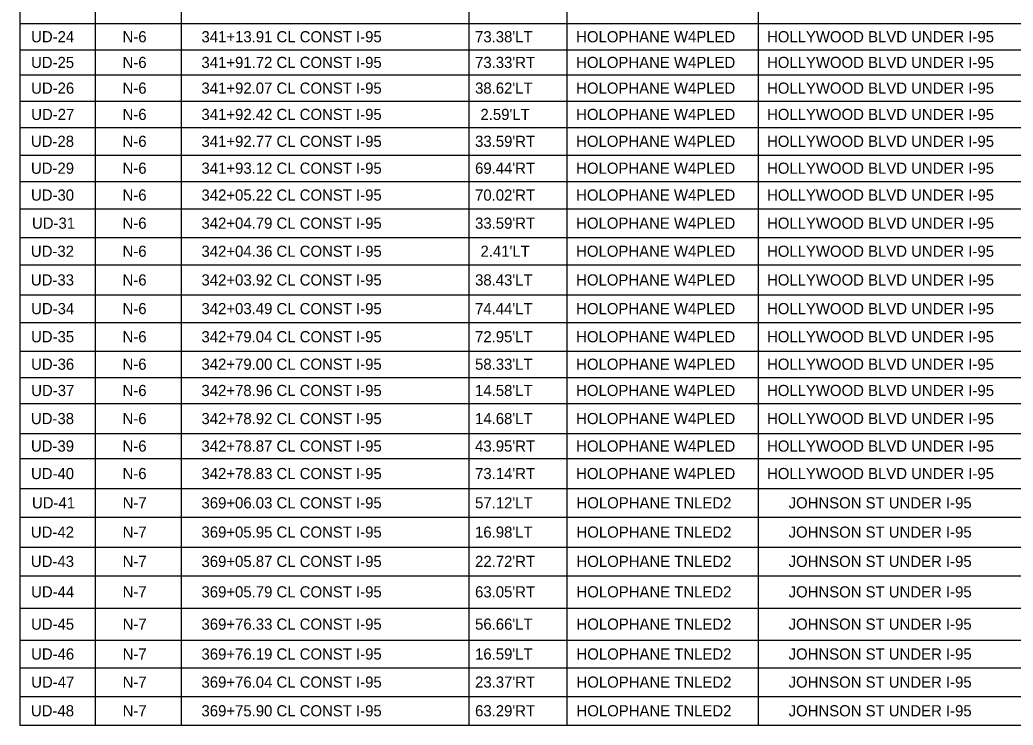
# Model space of a CAD drawing. Extents: x -816.7 to -727.6, y -2197.9 to -2187.8.
# Drawn here: x -777.1 to -770.86, y -2196.68 to -2192.25 of the extents above; entities that cross this region are included whole.
import ezdxf

# ---------------------------------------------------------------- set-up
doc = ezdxf.new("R2010")
doc.units = 0
for name, color, linetype in [('ClipBorder_dp', 7, 'Continuous'), ('MatchLines_dp', 7, 'Continuous'), ('NorthArw_dp', 7, 'Continuous'), ('Scale_dp', 7, 'Continuous')]:
    doc.layers.add(name, color=color, linetype=linetype)

msp = doc.modelspace()

# ---------------------------------------------------------------- linework, layer by layer
at = {"layer": 'MatchLines_dp'}
for p, q in [((-777.0968, -2192.2736), (-767.3318, -2192.2736)), ((-777.0968, -2192.2736), (-767.3318, -2192.2736)), ((-777.0968, -2192.4386), (-767.3318, -2192.4386)), ((-777.0968, -2192.4386), (-767.3318, -2192.4386)), ((-777.0968, -2192.5961), (-767.3318, -2192.5961)), ((-777.0968, -2192.5961), (-767.3318, -2192.5961)), ((-777.0968, -2192.7611), (-767.3318, -2192.7611)), ((-777.0968, -2192.7611), (-767.3318, -2192.7611)), ((-777.0968, -2192.9261), (-767.3318, -2192.9261)), ((-777.0968, -2192.9261), (-767.3318, -2192.9261)), ((-777.0968, -2193.0986), (-767.3318, -2193.0986)), ((-777.0968, -2193.0986), (-767.3318, -2193.0986)), ((-777.0968, -2193.2636), (-767.3318, -2193.2636)), ((-777.0968, -2193.2636), (-767.3318, -2193.2636)), ((-777.0968, -2193.4361), (-767.3318, -2193.4361)), ((-777.0968, -2193.4361), (-767.3318, -2193.4361)), ((-777.0968, -2193.6161), (-767.3318, -2193.6161)), ((-777.0968, -2193.6161), (-767.3318, -2193.6161)), ((-777.0968, -2193.7886), (-767.3318, -2193.7886)), ((-777.0968, -2193.7886), (-767.3318, -2193.7886)), ((-777.0968, -2193.9761), (-767.3318, -2193.9761)), ((-777.0968, -2193.9761), (-767.3318, -2193.9761)), ((-777.0968, -2194.1486), (-767.3318, -2194.1486)), ((-777.0968, -2194.1486), (-767.3318, -2194.1486)), ((-777.0968, -2194.3286), (-767.3318, -2194.3286)), ((-777.0968, -2194.3286), (-767.3318, -2194.3286)), ((-777.0968, -2194.4936), (-767.3318, -2194.4936)), ((-777.0968, -2194.4936), (-767.3318, -2194.4936)), ((-777.0968, -2194.6586), (-767.3318, -2194.6586)), ((-777.0968, -2194.6586), (-767.3318, -2194.6586)), ((-777.0968, -2194.8461), (-767.3318, -2194.8461)), ((-777.0968, -2194.8461), (-767.3318, -2194.8461)), ((-777.0968, -2195.0036), (-767.3318, -2195.0036)), ((-777.0968, -2195.0036), (-767.3318, -2195.0036)), ((-777.0968, -2195.1911), (-767.3318, -2195.1911)), ((-777.0968, -2195.1911), (-767.3318, -2195.1911)), ((-777.0968, -2195.3711), (-767.3318, -2195.3711)), ((-777.0968, -2195.3711), (-767.3318, -2195.3711)), ((-777.0968, -2195.5586), (-767.3318, -2195.5586)), ((-777.0968, -2195.5586), (-767.3318, -2195.5586)), ((-777.0968, -2195.7386), (-767.3318, -2195.7386)), ((-777.0968, -2195.7386), (-767.3318, -2195.7386)), ((-777.0968, -2195.9411), (-767.3318, -2195.9411)), ((-777.0968, -2195.9411), (-767.3318, -2195.9411)), ((-777.0968, -2196.1436), (-767.3318, -2196.1436)), ((-777.0968, -2196.1436), (-767.3318, -2196.1436)), ((-777.0968, -2196.3161), (-767.3318, -2196.3161)), ((-777.0968, -2196.3161), (-767.3318, -2196.3161)), ((-777.0968, -2196.4961), (-767.3318, -2196.4961)), ((-777.0968, -2196.4961), (-767.3318, -2196.4961))]:
    msp.add_line(p, q, dxfattribs=at)
at = {"layer": 'NorthArw_dp'}
for p, q in [((-777.0968, -2187.7736), (-777.0968, -2196.6761)), ((-777.0968, -2196.6761), (-767.3318, -2196.6761))]:
    msp.add_line(p, q, dxfattribs=at)
at = {"layer": 'Scale_dp'}
for p, q in [((-776.6243, -2188.1486), (-776.6243, -2196.6761)), ((-776.6243, -2188.1486), (-776.6243, -2196.6761)), ((-776.0843, -2188.1486), (-776.0843, -2196.6761)), ((-776.0843, -2188.1486), (-776.0843, -2196.6761)), ((-774.2768, -2188.1486), (-774.2768, -2196.6761)), ((-773.6618, -2188.1486), (-773.6618, -2196.6761)), ((-773.6618, -2188.1486), (-773.6618, -2196.6761)), ((-772.4618, -2188.1486), (-772.4618, -2196.6761)), ((-772.4618, -2188.1486), (-772.4618, -2196.6761)), ((-774.2768, -2189.4686), (-774.2768, -2196.6761))]:
    msp.add_line(p, q, dxfattribs=at)

# ---------------------------------------------------------------- texts
at = {"layer": 'ClipBorder_dp'}
for s, p in [('UD-24', (-777.0261, -2192.3911)), ('N-6', (-776.4521, -2192.3911)), ('341+13.91 CL CONST I-95', (-775.9564, -2192.3911)), ("73.38'LT", (-774.2386, -2192.3911)), ('HOLOPHANE W4PLED', (-773.6036, -2192.3911)), ('HOLLYWOOD BLVD UNDER I-95', (-772.4054, -2192.3911)), ('UD-25', (-777.0266, -2192.5523)), ('N-6', (-776.4521, -2192.5523)), ('341+91.72 CL CONST I-95', (-775.9564, -2192.5523)), ("73.33'RT", (-774.2386, -2192.5523)), ('HOLOPHANE W4PLED', (-773.6036, -2192.5523)), ('HOLLYWOOD BLVD UNDER I-95', (-772.4054, -2192.5523)), ('UD-26', (-777.0261, -2192.7136)), ('N-6', (-776.4521, -2192.7136)), ('341+92.07 CL CONST I-95', (-775.9564, -2192.7136)), ("38.62'LT", (-774.2386, -2192.7136)), ('HOLOPHANE W4PLED', (-773.6036, -2192.7136)), ('HOLLYWOOD BLVD UNDER I-95', (-772.4054, -2192.7136)), ('UD-27', (-777.0255, -2192.8786)), ('N-6', (-776.4521, -2192.8786)), ('341+92.42 CL CONST I-95', (-775.9564, -2192.8786)), ("2.59'LT", (-774.2047, -2192.8786)), ('HOLOPHANE W4PLED', (-773.6036, -2192.8786)), ('HOLLYWOOD BLVD UNDER I-95', (-772.4054, -2192.8786)), ('UD-28', (-777.0272, -2193.0473)), ('N-6', (-776.4521, -2193.0473)), ('341+92.77 CL CONST I-95', (-775.9564, -2193.0473)), ("33.59'RT", (-774.2386, -2193.0473)), ('HOLOPHANE W4PLED', (-773.6036, -2193.0473)), ('HOLLYWOOD BLVD UNDER I-95', (-772.4054, -2193.0473)), ('UD-29', (-777.0271, -2193.2161)), ('N-6', (-776.4521, -2193.2161)), ('341+93.12 CL CONST I-95', (-775.9564, -2193.2161)), ("69.44'RT", (-774.2386, -2193.2161)), ('HOLOPHANE W4PLED', (-773.6036, -2193.2161)), ('HOLLYWOOD BLVD UNDER I-95', (-772.4054, -2193.2161)), ('UD-30', (-777.0269, -2193.3848)), ('N-6', (-776.4521, -2193.3848)), ('342+05.22 CL CONST I-95', (-775.9564, -2193.3848)), ("70.02'RT", (-774.2386, -2193.3848)), ('HOLOPHANE W4PLED', (-773.6036, -2193.3848)), ('HOLLYWOOD BLVD UNDER I-95', (-772.4054, -2193.3848)), ('UD-31', (-777.0208, -2193.5611)), ('N-6', (-776.4521, -2193.5611)), ('342+04.79 CL CONST I-95', (-775.9564, -2193.5611)), ("33.59'RT", (-774.2386, -2193.5611)), ('HOLOPHANE W4PLED', (-773.6036, -2193.5611)), ('HOLLYWOOD BLVD UNDER I-95', (-772.4054, -2193.5611)), ('UD-32', (-777.0275, -2193.7373)), ('N-6', (-776.4521, -2193.7373)), ('342+04.36 CL CONST I-95', (-775.9564, -2193.7373)), ("2.41'LT", (-774.2047, -2193.7373)), ('HOLOPHANE W4PLED', (-773.6036, -2193.7373)), ('HOLLYWOOD BLVD UNDER I-95', (-772.4054, -2193.7373)), ('UD-33', (-777.0275, -2193.9173)), ('N-6', (-776.4521, -2193.9173)), ('342+03.92 CL CONST I-95', (-775.9564, -2193.9173)), ("38.43'LT", (-774.2386, -2193.9173)), ('HOLOPHANE W4PLED', (-773.6036, -2193.9173)), ('HOLLYWOOD BLVD UNDER I-95', (-772.4054, -2193.9173)), ('UD-34', (-777.0261, -2194.0973)), ('N-6', (-776.4521, -2194.0973)), ('342+03.49 CL CONST I-95', (-775.9564, -2194.0973)), ("74.44'LT", (-774.2386, -2194.0973)), ('HOLOPHANE W4PLED', (-773.6036, -2194.0973)), ('HOLLYWOOD BLVD UNDER I-95', (-772.4054, -2194.0973)), ('UD-35', (-777.0266, -2194.2736)), ('N-6', (-776.4521, -2194.2736)), ('342+79.04 CL CONST I-95', (-775.9564, -2194.2736)), ("72.95'LT", (-774.2386, -2194.2736)), ('HOLOPHANE W4PLED', (-773.6036, -2194.2736)), ('HOLLYWOOD BLVD UNDER I-95', (-772.4054, -2194.2736)), ('UD-36', (-777.0261, -2194.4461)), ('N-6', (-776.4521, -2194.4461)), ('342+79.00 CL CONST I-95', (-775.9564, -2194.4461)), ("58.33'LT", (-774.2386, -2194.4461)), ('HOLOPHANE W4PLED', (-773.6036, -2194.4461)), ('HOLLYWOOD BLVD UNDER I-95', (-772.4054, -2194.4461)), ('UD-37', (-777.0255, -2194.6111)), ('N-6', (-776.4521, -2194.6111)), ('342+78.96 CL CONST I-95', (-775.9564, -2194.6111)), ("14.58'LT", (-774.2386, -2194.6111)), ('HOLOPHANE W4PLED', (-773.6036, -2194.6111)), ('HOLLYWOOD BLVD UNDER I-95', (-772.4054, -2194.6111)), ('UD-38', (-777.0272, -2194.7873)), ('N-6', (-776.4521, -2194.7873)), ('342+78.92 CL CONST I-95', (-775.9564, -2194.7873)), ("14.68'LT", (-774.2386, -2194.7873)), ('HOLOPHANE W4PLED', (-773.6036, -2194.7873)), ('HOLLYWOOD BLVD UNDER I-95', (-772.4054, -2194.7873)), ('UD-39', (-777.0271, -2194.9598)), ('N-6', (-776.4521, -2194.9598)), ('342+78.87 CL CONST I-95', (-775.9564, -2194.9598)), ("43.95'RT", (-774.2386, -2194.9598)), ('HOLOPHANE W4PLED', (-773.6036, -2194.9598)), ('HOLLYWOOD BLVD UNDER I-95', (-772.4054, -2194.9598)), ('UD-40', (-777.0269, -2195.1323)), ('N-6', (-776.4521, -2195.1323)), ('342+78.83 CL CONST I-95', (-775.9564, -2195.1323)), ("73.14'RT", (-774.2386, -2195.1323)), ('HOLOPHANE W4PLED', (-773.6036, -2195.1323)), ('HOLLYWOOD BLVD UNDER I-95', (-772.4054, -2195.1323)), ('UD-41', (-777.0208, -2195.3161)), ('N-7', (-776.4515, -2195.3161)), ('369+06.03 CL CONST I-95', (-775.9564, -2195.3161)), ("57.12'LT", (-774.2386, -2195.3161)), ('HOLOPHANE TNLED2', (-773.6014, -2195.3161)), ('JOHNSON ST UNDER I-95', (-772.2699, -2195.3161)), ('UD-42', (-777.0275, -2195.4998)), ('N-7', (-776.4515, -2195.4998)), ('369+05.95 CL CONST I-95', (-775.9564, -2195.4998)), ("16.98'LT", (-774.2386, -2195.4998)), ('HOLOPHANE TNLED2', (-773.6014, -2195.4998)), ('JOHNSON ST UNDER I-95', (-772.2699, -2195.4998)), ('UD-43', (-777.0275, -2195.6836)), ('N-7', (-776.4515, -2195.6836)), ('369+05.87 CL CONST I-95', (-775.9564, -2195.6836)), ("22.72'RT", (-774.2386, -2195.6836)), ('HOLOPHANE TNLED2', (-773.6014, -2195.6836)), ('JOHNSON ST UNDER I-95', (-772.2699, -2195.6836)), ('UD-44', (-777.0261, -2195.8748)), ('N-7', (-776.4515, -2195.8748)), ('369+05.79 CL CONST I-95', (-775.9564, -2195.8748)), ("63.05'RT", (-774.2386, -2195.8748)), ('HOLOPHANE TNLED2', (-773.6014, -2195.8748)), ('JOHNSON ST UNDER I-95', (-772.2699, -2195.8748)), ('UD-45', (-777.0266, -2196.0773)), ('N-7', (-776.4515, -2196.0773)), ('369+76.33 CL CONST I-95', (-775.9564, -2196.0773)), ("56.66'LT", (-774.2386, -2196.0773)), ('HOLOPHANE TNLED2', (-773.6014, -2196.0773)), ('JOHNSON ST UNDER I-95', (-772.2699, -2196.0773)), ('UD-46', (-777.0261, -2196.2648)), ('N-7', (-776.4515, -2196.2648)), ('369+76.19 CL CONST I-95', (-775.9564, -2196.2648)), ("16.59'LT", (-774.2386, -2196.2648)), ('HOLOPHANE TNLED2', (-773.6014, -2196.2648)), ('JOHNSON ST UNDER I-95', (-772.2699, -2196.2648)), ('UD-47', (-777.0255, -2196.4411)), ('N-7', (-776.4515, -2196.4411)), ('369+76.04 CL CONST I-95', (-775.9564, -2196.4411)), ("23.37'RT", (-774.2386, -2196.4411)), ('HOLOPHANE TNLED2', (-773.6014, -2196.4411)), ('JOHNSON ST UNDER I-95', (-772.2699, -2196.4411)), ('UD-48', (-777.0272, -2196.6211)), ('N-7', (-776.4515, -2196.6211)), ('369+75.90 CL CONST I-95', (-775.9564, -2196.6211)), ("63.29'RT", (-774.2386, -2196.6211)), ('HOLOPHANE TNLED2', (-773.6014, -2196.6211)), ('JOHNSON ST UNDER I-95', (-772.2699, -2196.6211))]:
    msp.add_text(s, height=0.07, dxfattribs=at).set_placement(p)

doc.saveas('drawing.dxf')
